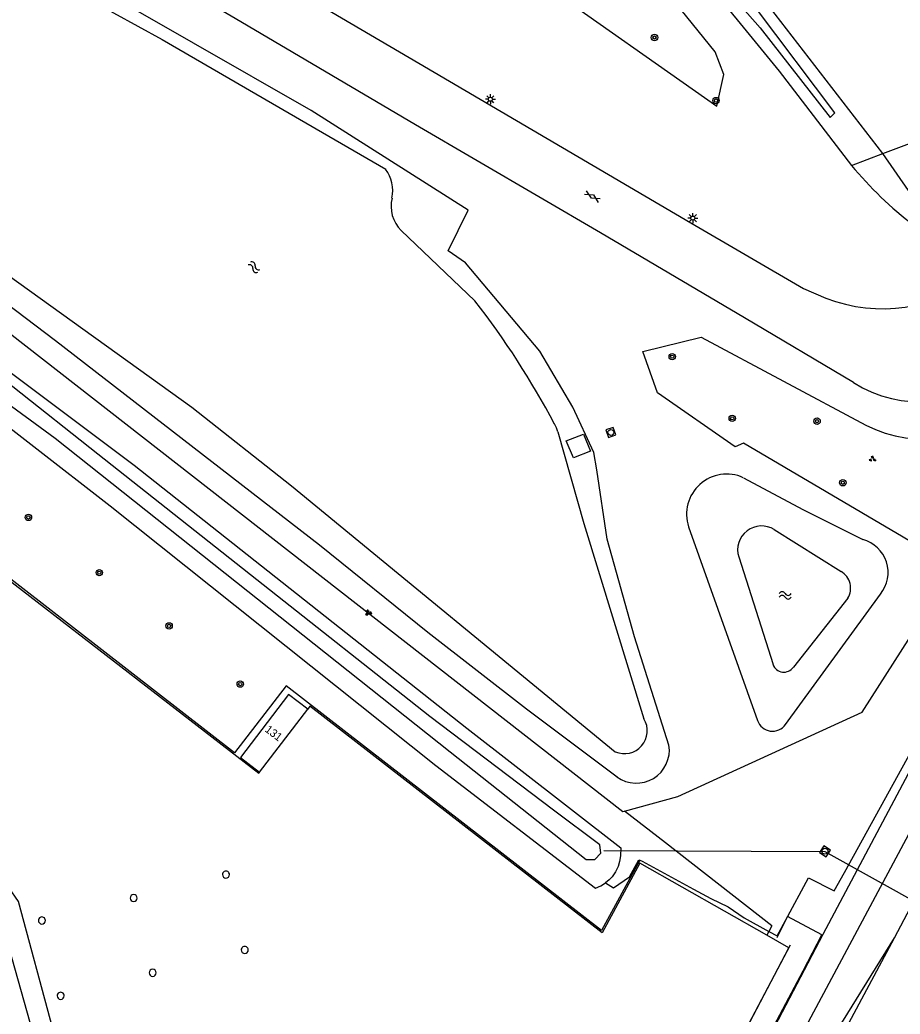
# Model space of a CAD drawing. Extents: x 136000 to 138005, y 398500 to 400500.
# Drawn here: x 136630.1 to 136740.1, y 398735.3 to 398859.5 of the extents above; entities that cross this region are included whole.
import ezdxf

# ---------------------------------------------------------------- set-up
doc = ezdxf.new("R2010")
doc.units = 0
for name, color, linetype in [('gg-afsc-erfafscheiding', 7, 'Continuous'), ('gg-afsc-faunaraster', 7, 'Continuous'), ('gg-afsc-hekwerk', 7, 'Continuous'), ('gg-anno-huisnummerreeks BGT', 7, 'Continuous'), ('gg-aspt-spoorlijn', 7, 'Continuous'), ('gg-bbg-hoofdgebouw', 7, 'Continuous'), ('gg-bbg-hoogspanningsmast', 7, 'Continuous'), ('gg-knt-bronhoudergrens', 7, 'Continuous'), ('gg-knt-verharding', 7, 'Continuous'), ('gg-kntw-bovenkant insteek waterloop', 7, 'Continuous'), ('gg-kntw-greppel-droge sloot', 7, 'Continuous'), ('gg-kntw-waterlijn', 7, 'Continuous'), ('gg-kwrk-duiker nz buis', 7, 'Continuous'), ('gg-kwrk-uitstroombak niveau min 01', 7, 'Continuous'), ('gt-grn-groengrens', 7, 'Continuous'), ('gt-symb-boom', 7, 'Continuous'), ('gt-symb-gesloten verharding', 7, 'Continuous'), ('gt-symb-groenvak', 7, 'Continuous'), ('gt-symb-lichtmast', 7, 'Continuous'), ('gt-symb-rioolschacht', 7, 'Continuous'), ('gt-symb-watersymbool', 7, 'Continuous'), ('gx-grn-maaiveld', 7, 'Continuous')]:
    doc.layers.add(name, color=color, linetype=linetype)

# ---------------------------------------------------------------- blocks, each defined once
blk = doc.blocks.new('gt0-WA')
at = {"layer": 'gt-symb-watersymbool'}
for centre, start, end in [((-0.32, 0.02), 28.0725, 151.9275), ((0.43, 0.42), 208.0725, 331.9275), ((-0.32, -0.43), 28.0725, 151.9275), ((0.43, -0.03), 208.0725, 331.9275)]:
    blk.add_arc(centre, 0.425, start, end, dxfattribs=at)
blk = doc.blocks.new('gt0-LMAST')
at = {"layer": 'gt-symb-lichtmast'}
for p, q in [((-0.18, 0.17), (-0.45, 0.44)), ((-0.01, 0.25), (-0.01, 0.62)), ((0.17, 0.17), (0.44, 0.44)), ((-0.26, 0), (-0.63, 0)), ((-0.18, -0.18), (-0.45, -0.45)), ((-0.01, -0.25), (-0.01, -0.63)), ((0.44, -0.45), (0.17, -0.18)), ((0.24, 0), (0.62, 0))]:
    blk.add_line(p, q, dxfattribs=at)
blk.add_circle((-0.01, 0), 0.25, dxfattribs=at)
blk = doc.blocks.new('gt0-GESVH1')
at = {"layer": 'gt-symb-gesloten verharding'}
for p, q in [((-0.99, -0.26), (0.01, 0.24)), ((0.01, -0.26), (-0.99, 0.24)), ((0.01, 0.24), (1.01, -0.26)), ((1.01, 0.24), (0.01, -0.26))]:
    blk.add_line(p, q, dxfattribs=at)
blk = doc.blocks.new('gt0-BOOM')
at = {"layer": 'gt-symb-boom'}
for radius in [0.4, 0.2]:
    blk.add_circle((0, 0), radius, dxfattribs=at)
blk = doc.blocks.new('gt0-RS')
at = {"layer": 'gt-symb-rioolschacht'}
blk.add_lwpolyline([(-0.5, -0.5), (0.5, -0.5), (0.5, 0.5), (-0.5, 0.5)], close=True, dxfattribs=at)
blk.add_circle((0, 0), 0.375, dxfattribs=at)
blk = doc.blocks.new('gt0-GRVAK')
at = {"layer": 'gt-symb-groenvak'}
for p, q in [((-0.11, 0.19), (-0.23, 0.24)), ((-0.18, 0.15), (0.09, 0.15)), ((-0.09, 0.21), (-0.16, 0.32)), ((-0.05, 0.21), (-0.05, 0.39)), ((0, 0.21), (0.06, 0.32)), ((0.01, 0.19), (0.13, 0.24)), ((0.26, -0.05), (0.2, 0.06)), ((0.3, -0.05), (0.3, 0.13)), ((0.35, -0.05), (0.41, 0.06)), ((-0.24, -0.23), (-0.36, -0.18)), ((-0.32, -0.26), (-0.05, -0.26)), ((-0.23, -0.21), (-0.29, -0.1)), ((-0.18, -0.2), (-0.18, -0.02)), ((-0.14, -0.21), (-0.07, -0.1)), ((-0.12, -0.23), (0, -0.18)), ((0.24, -0.07), (0.12, -0.02)), ((0.17, -0.11), (0.44, -0.11)), ((0.37, -0.07), (0.49, -0.02))]:
    blk.add_line(p, q, dxfattribs=at)

msp = doc.modelspace()

# ---------------------------------------------------------------- linework, layer by layer
at = {"layer": 'gg-afsc-erfafscheiding'}
for p, q in [((136737.92, 398842.77), (136753.88, 398848.91)), ((136733.99, 398841.3), (136737.92, 398842.77))]:
    msp.add_line(p, q, dxfattribs=at)
at = {"layer": 'gg-afsc-faunaraster'}
for points in [[(136564.65, 398984.36), (136588.81, 398970.45), (136601.21, 398962.65), (136618.79, 398951.86), (136639.23, 398937.6), (136650.94, 398928.3), (136662.25, 398918.61), (136674.52, 398906.86), (136686.63, 398895.42), (136698.64, 398884), (136713.9, 398866.63), (136724.94, 398853.08), (136733.99, 398841.3)], [(136614.1, 398831.92), (136614.17, 398831.75), (136705.44, 398760.59), (136705.63, 398760.65)], [(136705.63, 398760.65), (136712.31, 398762.47), (136735.34, 398772.99), (136764.65, 398818.87), (136758.02, 398823.56), (136759.65, 398825.56), (136758.93, 398825.92)]]:
    msp.add_lwpolyline(points, dxfattribs=at)
msp.add_arc((136770.31, 398871.31), 47.11, 219.5597, 232.7087, dxfattribs=at)
at = {"layer": 'gg-afsc-hekwerk'}
msp.add_line((136724.03, 398746.32), (136723.66, 398745.62), dxfattribs=at)
for points in [[(136723.66, 398745.62), (136724.71, 398745.05), (136725.76, 398746.96), (136728.61, 398752.29), (136731.82, 398750.7), (136733.1, 398752.97), (136767.08, 398814.64), (136772.08, 398823.55)], [(136707.55, 398754.51), (136702.78, 398745.73), (136663.37, 398776.28), (136656.93, 398767.93), (136617.02, 398798.85), (136612.34, 398803.26)], [(136703.27, 398751.67), (136704.25, 398751.06), (136706.24, 398752.43), (136707.44, 398754.55), (136707.55, 398754.51)], [(136707.55, 398754.51), (136707.83, 398754.4), (136714.24, 398750.88), (136716.4, 398749.74), (136718.57, 398748.68), (136720.6, 398747.3), (136723.66, 398745.62)], [(136723.23, 398731.82), (136727.94, 398740.67), (136730.3, 398745.17), (136726, 398747.46), (136724.65, 398744.82)]]:
    msp.add_lwpolyline(points, dxfattribs=at)
at = {"layer": 'gg-aspt-spoorlijn'}
for p, q in [((136724.33, 398720.62), (136739.35, 398744.81)), ((136725.87, 398719.6), (136739.35, 398744.81)), ((136726.18, 398743.57), (136726.37, 398743.95))]:
    msp.add_line(p, q, dxfattribs=at)
for points in [[(136739.35, 398744.81), (136749.75, 398764.46), (136761.08, 398785.58), (136792.46, 398844.68), (136807.63, 398872.92), (136815.69, 398887.7), (136848.2, 398946.28), (136862.67, 398972.66), (136907.32, 399056.5), (137071.02, 399364.84)], [(136718.68, 398715.71), (136749.17, 398772.79), (136771.72, 398813.75), (136790.56, 398849.19)], [(136648.44, 398647.8), (136648.37, 398655.45), (136648.08, 398660.63), (136647.47, 398667.07), (136646.58, 398673.41), (136645.52, 398679.2), (136643.92, 398686.49), (136640.6, 398699.3), (136632.12, 398731.69), (136627.68, 398747.39), (136625.61, 398754.43), (136623.74, 398760.14), (136621.77, 398765.32), (136620.35, 398768.38)], [(136647.39, 398596.93), (136652.93, 398607.25), (136659.67, 398618.72), (136664.05, 398626.69), (136667.4, 398633.1), (136707.6, 398708.32), (136726.37, 398743.95)], [(136672.23, 398641.82), (136678.74, 398654.11), (136689.97, 398675.09), (136698.64, 398691.55), (136707.6, 398708.32), (136715.54, 398723.31), (136726.18, 398743.57)]]:
    msp.add_lwpolyline(points, dxfattribs=at)
at = {"layer": 'gg-bbg-hoofdgebouw'}
msp.add_line((136660.06, 398765.5), (136666.06, 398773.39), dxfattribs=at)
msp.add_lwpolyline([(136666.06, 398773.39), (136663.67, 398775.21), (136657.67, 398767.32), (136660.06, 398765.5)], dxfattribs=at)
at = {"layer": 'gg-bbg-hoogspanningsmast'}
for centre, radius, start, end in [((136655.85, 398752.71), 0.442, 0.1296, 180.1296), ((136655.85, 398752.71), 0.442, 180.1296, 0.1296), ((136644.33, 398749.78), 0.442, 360, 180), ((136644.33, 398749.78), 0.442, 180, 0), ((136632.86, 398746.98), 0.443, 359.9353, 180.0647), ((136632.86, 398746.98), 0.443, 180.0647, 359.9353), ((136658.2, 398743.3), 0.442, 0.1296, 180.1296), ((136658.2, 398743.3), 0.442, 180.1296, 0.1296), ((136646.7, 398740.44), 0.442, 360, 180), ((136646.7, 398740.44), 0.442, 180, 0), ((136635.21, 398737.57), 0.442, 0.1298, 180.259), ((136635.21, 398737.57), 0.442, 180.259, 0.1298)]:
    msp.add_arc(centre, radius, start, end, dxfattribs=at)
at = {"layer": 'gg-knt-bronhoudergrens'}
msp.add_line((136723.66, 398745.62), (136723.4, 398745.15), dxfattribs=at)
at = {"layer": 'gg-knt-verharding'}
for p, q in [((136660.06, 398765.5), (136659.94, 398765.34)), ((136726.18, 398743.57), (136723.4, 398745.15))]:
    msp.add_line(p, q, dxfattribs=at)
for points in [[(136637.19, 398879.2), (136679.96, 398854.07), (136713.93, 398834.13), (136728.01, 398825.91), (136730.79, 398824.72)], [(136734.25, 398814.2), (136720.64, 398822.26), (136702.62, 398832.87), (136679.53, 398846.38), (136657, 398859.64), (136635.93, 398871.97)], [(136659.94, 398765.34), (136618.1, 398797.67), (136615.47, 398799.91), (136612.19, 398803.11)], [(136702.84, 398745.44), (136666.33, 398773.74), (136666.06, 398773.39)], [(136723.4, 398745.15), (136707.54, 398754.15), (136702.84, 398745.44)]]:
    msp.add_lwpolyline(points, dxfattribs=at)
for centre, radius, start, end in [((136737.83, 398842.56), 19.17, 248.4694, 308.8177), ((136742.4, 398826.71), 14.93, 236.9286, 314.9935)]:
    msp.add_arc(centre, radius, start, end, dxfattribs=at)
at = {"layer": 'gg-kntw-bovenkant insteek waterloop'}
for p, q in [((136713.65, 398796.16), (136722.24, 398771.95)), ((136725.74, 398771.45), (136737.61, 398787.76))]:
    msp.add_line(p, q, dxfattribs=at)
for points in [[(136737.92, 398842.77), (136717.37, 398869.39), (136691.65, 398897.6), (136661.47, 398926.2), (136625.51, 398953.67)], [(136711.18, 398768.88), (136706.87, 398782.42), (136703.48, 398794.6), (136702.2, 398803.26), (136701.81, 398805.43), (136699.18, 398811.11), (136695.07, 398818.08), (136685.76, 398829.14), (136683.63, 398830.64), (136686.09, 398835.71), (136666.49, 398848.15), (136637.1, 398865.01), (136634.84, 398866.12)], [(136594.22, 398830.95), (136596.97, 398835.7), (136621.88, 398820.72), (136644.39, 398803.86), (136685.96, 398771), (136705.17, 398756.05), (136705.14, 398755.05), (136705.03, 398754.35), (136704.84, 398753.72), (136704.51, 398753.04), (136704.09, 398752.45), (136703.71, 398752.04), (136703.27, 398751.67)], [(136617.8, 398832.92), (136620.72, 398829.89), (136634.54, 398819.42), (136667.52, 398793.9), (136681.08, 398783.01), (136693.39, 398773.43), (136704.7, 398764.92)], [(136622.28, 398813.58), (136641.38, 398798.79), (136682.09, 398766.33), (136702.02, 398751.02), (136702.67, 398751.3), (136703.27, 398751.67)], [(136720.48, 398802.29), (136727.9, 398798.3), (136735.4, 398794.58)]]:
    msp.add_lwpolyline(points, dxfattribs=at)
for centre, radius, start, end in [((136718.4, 398797.73), 5.01, 65.4862, 198.3603), ((136734.29, 398790.45), 4.27, 320.9386, 74.8895), ((136724.13, 398772.62), 2, 199.5441, 323.9804), ((136707.12, 398768.25), 4.12, 233.9732, 8.8745)]:
    msp.add_arc(centre, radius, start, end, dxfattribs=at)
at = {"layer": 'gg-kntw-greppel-droge sloot'}
msp.add_line((136743.09, 398835.3), (136737.92, 398842.77), dxfattribs=at)
at = {"layer": 'gg-kntw-waterlijn'}
for p, q in [((136677.73, 398833.18), (136686.96, 398824.4)), ((136624.77, 398830.35), (136651.61, 398811.09)), ((136651.61, 398811.09), (136664.06, 398801.27)), ((136697.31, 398808.02), (136700.57, 398796.56)), ((136664.06, 398801.27), (136704.49, 398768.06)), ((136700.57, 398796.56), (136708.07, 398772.15)), ((136724.35, 398795.81), (136732.68, 398790.57)), ((136719.9, 398792.39), (136724.19, 398778.96)), ((136733.53, 398787.23), (136726.74, 398778.64))]:
    msp.add_line(p, q, dxfattribs=at)
for points in [[(136731.91, 398847.88), (136722.11, 398860.88), (136711.19, 398874.09), (136701.41, 398885.21), (136690.95, 398895.68), (136664.08, 398921.61), (136648.47, 398934.68), (136632.16, 398946.88), (136616.49, 398957.56), (136594.63, 398971.38), (136566.22, 398986.85), (136565.48, 398986.18), (136565.85, 398985.41), (136574.23, 398980.95), (136592.99, 398970.48), (136606.66, 398961.82), (136633.17, 398944.38), (136663.15, 398920.83), (136693.8, 398891.07), (136722.57, 398858.48), (136731.32, 398847.3), (136731.91, 398847.88)], [(136635.73, 398863.73), (136647.88, 398857.02), (136667.9, 398845.41), (136675.81, 398840.83)], [(136596.46, 398832.4), (136609.41, 398824.11), (136619.82, 398817.98), (136634.51, 398807.22), (136683.88, 398768.05), (136700.86, 398754.58), (136701.93, 398754.6), (136702.67, 398755.38), (136702.56, 398756.44), (136696.76, 398760.74), (136681.32, 398772.47), (136659.7, 398789.55), (136639.83, 398805.25), (136629.23, 398813.62), (136621.39, 398818.98), (136611.38, 398824.66), (136597.15, 398833.64), (136596.46, 398832.4)]]:
    msp.add_lwpolyline(points, dxfattribs=at)
for centre, radius, start, end in [((136672.13, 398838.14), 4.55, 348.3582, 36.1806), ((136680.72, 398836.2), 4.25, 166.0753, 225.268), ((136601.27, 398758.11), 108.33, 28.0173, 37.7265), ((136692.51, 398806.65), 4.99, 15.9436, 28.1026), ((136722.76, 398793.27), 2.99, 57.937, 197.1143), ((136731.47, 398788.49), 2.41, 328.4537, 59.8604), ((136725.54, 398779.44), 1.44, 199.7632, 326.02), ((136705.62, 398770.68), 2.86, 246.6535, 31.0856)]:
    msp.add_arc(centre, radius, start, end, dxfattribs=at)
at = {"layer": 'gg-kwrk-duiker nz buis'}
msp.add_lwpolyline([(136703.05, 398755.7), (136730.68, 398755.61), (136755.44, 398741.83), (136729.48, 398682.89)], dxfattribs=at)
at = {"layer": 'gg-kwrk-uitstroombak niveau min 01'}
msp.add_lwpolyline([(136700.52, 398807.72), (136701.37, 398805.62), (136699.27, 398804.77), (136698.36, 398806.9), (136700.52, 398807.72)], dxfattribs=at)
at = {"layer": 'gt-grn-groengrens'}
for points in [[(136717.16, 398848.72), (136718.04, 398852.64), (136716.98, 398855.47), (136709.17, 398865.13), (136697.3, 398877.95), (136682.7, 398892.87), (136667.59, 398907.67), (136652.61, 398920.48), (136642.01, 398929.07), (136635.4, 398931.78), (136646.98, 398916.47), (136670.28, 398891.56), (136694.9, 398864.39), (136717.16, 398848.72)], [(136754.88, 398811.82), (136760.11, 398818.21), (136761.83, 398817.17), (136745.61, 398791.84), (136720.5, 398806.6), (136719.46, 398806.13), (136709.74, 398812.89), (136707.91, 398818.06), (136715.23, 398819.86), (136735.79, 398808.85)], [(136724.03, 398746.32), (136710.74, 398756.67), (136705.63, 398760.65)]]:
    msp.add_lwpolyline(points, dxfattribs=at)
msp.add_arc((136743.25, 398823.71), 16.64, 243.3322, 314.3535, dxfattribs=at)
at = {"layer": 'gx-grn-maaiveld'}
for points in [[(136672.23, 398641.82), (136672.24, 398641.81), (136675.35, 398640.22), (136699.13, 398685.08), (136716.05, 398716.78), (136722.5, 398729.27), (136722.07, 398729.49), (136723.48, 398731.99), (136730.47, 398745.28), (136747.13, 398776.71), (136751.67, 398785.06), (136753.92, 398788.95), (136758.85, 398796.76), (136769.93, 398812.85), (136774.87, 398819.27)], [(136649.95, 398647.78), (136650.1, 398654.09), (136649.85, 398658.34), (136648.65, 398670.88), (136646.33, 398683.38), (136640.43, 398705.95), (136634.48, 398727.88), (136633.16, 398733.21), (136634.21, 398733.44), (136629.92, 398749.36), (136628.73, 398751.09), (136626.81, 398758.34), (136624.85, 398764.13), (136622.32, 398770.23)]]:
    msp.add_lwpolyline(points, dxfattribs=at)

# ---------------------------------------------------------------- block references
at = {"layer": 'gt-symb-boom'}
for p in [(136709.38, 398857.28), (136717.07, 398849.4), (136711.6, 398817.41), (136719.09, 398809.7), (136729.69, 398809.35), (136732.91, 398801.66), (136631.18, 398797.33), (136640.03, 398790.43), (136648.75, 398783.78), (136657.64, 398776.51)]:
    msp.add_blockref('gt0-BOOM', p, dxfattribs=at)
at = {"layer": 'gt-symb-gesloten verharding', "rotation": -30.413230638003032}
msp.add_blockref('gt0-GESVH1', (136701.62, 398837.42), dxfattribs=at)
at = {"layer": 'gt-symb-groenvak', "rotation": -17.330108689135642}
msp.add_blockref('gt0-GRVAK', (136736.59, 398804.63), dxfattribs=at)
at = {"layer": 'gt-symb-groenvak'}
msp.add_blockref('gt0-GRVAK', (136673.64, 398785.43), dxfattribs=at)
at = {"layer": 'gt-symb-lichtmast'}
for p in [(136688.89, 398849.57), (136714.18, 398834.72)]:
    msp.add_blockref('gt0-LMAST', p, dxfattribs=at)
at = {"layer": 'gt-symb-rioolschacht'}
for p, rotation in [((136703.93, 398807.94), 19.033079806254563), ((136730.67, 398755.63), 57.39326330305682)]:
    msp.add_blockref('gt0-RS', p, dxfattribs=dict(at, rotation=rotation))
at = {"layer": 'gt-symb-watersymbool', "rotation": -37.729269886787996}
msp.add_blockref('gt0-WA', (136659.32, 398828.62), dxfattribs=at)
at = {"layer": 'gt-symb-watersymbool'}
msp.add_blockref('gt0-WA', (136725.65, 398787.59), dxfattribs=at)

# ---------------------------------------------------------------- texts
at = {"layer": 'gg-anno-huisnummerreeks BGT'}
msp.add_text('131', height=1, rotation=322.8, dxfattribs=at).set_placement((136660.63, 398770.66))

doc.saveas('drawing.dxf')
